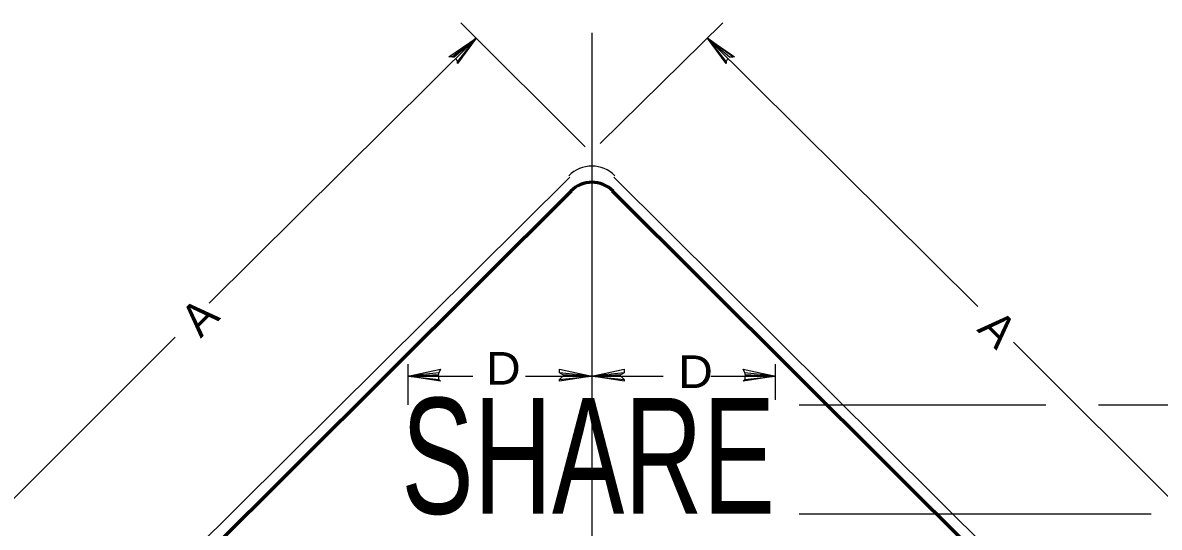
# Model space of a CAD drawing. Extents: x -0.018 to 0.195, y -0.006 to 0.263.
# Drawn here: x 0.0462 to 0.1297, y 0.1654 to 0.2025 of the extents above; entities that cross this region are included whole.
import ezdxf
from ezdxf.enums import TextEntityAlignment as Align

# ---------------------------------------------------------------- set-up
doc = ezdxf.new("R2010")
doc.units = 0
doc.header["$LTSCALE"] = 0.00096
doc.linetypes.add('DOT_DASHED', pattern=[7.7, 5, -1.2, 0.3, -1.2])
doc.layers.add('1', color=7, linetype='Continuous', lineweight=25)
doc.layers.add('12', color=7, linetype='Continuous', lineweight=13)

msp = doc.modelspace()

# ---------------------------------------------------------------- linework, layer by layer
at = {"layer": '1'}
for p, q in [((0.078375, 0.2025), (0.0875, 0.193375)), ((0.088625, 0.193625), (0.097625, 0.2025)), ((0.059875, 0.181875), (0.0795, 0.201375)), ((0.0965, 0.201375), (0.116375, 0.181625)), ((0.037, 0.159), (0.057375, 0.179375)), ((0.119, 0.179), (0.139, 0.159)), ((0.12525, 0.174375), (0.143, 0.174375)), ((0.10325, 0.166375), (0.129125, 0.166375))]:
    msp.add_line(p, q, dxfattribs=at)
at = {"layer": '1', "linetype": 'DOT_DASHED'}
msp.add_line((0.088, 0.20175), (0.088, 0.10525), dxfattribs=at)
at = {"layer": '1'}
for points in [[(0.07775, 0.2), (0.077875, 0.2), (0.0795, 0.201375), (0.07775, 0.2), (0.0775, 0.2), (0.0795, 0.201375), (0.078, 0.199875), (0.078125, 0.199625), (0.0795, 0.201375), (0.078125, 0.1995), (0.078125, 0.199625)], [(0.097875, 0.199625), (0.098, 0.199875), (0.0965, 0.201375), (0.097875, 0.199625), (0.097875, 0.1995), (0.0965, 0.201375), (0.098125, 0.2), (0.098375, 0.2), (0.0965, 0.201375), (0.0985, 0.2), (0.098375, 0.2)]]:
    msp.add_lwpolyline(points, dxfattribs=at)
at = {"layer": '12', "lineweight": 25}
for p, q in [((0.04725, 0.15225), (0.086375, 0.191125)), ((0.089625, 0.191125), (0.12875, 0.15225)), ((0.0745, 0.174375), (0.0745, 0.177375)), ((0.1015, 0.17475), (0.1015, 0.177375)), ((0.0745, 0.1765), (0.07925, 0.1765)), ((0.09675, 0.1765), (0.1015, 0.1765)), ((0.10325, 0.174375), (0.121375, 0.174375))]:
    msp.add_line(p, q, dxfattribs=at)
at = {"layer": '12', "lineweight": 60}
for p, q in [((0.048375, 0.152125), (0.0865, 0.190125)), ((0.0895, 0.190125), (0.127625, 0.152125))]:
    msp.add_line(p, q, dxfattribs=at)
at = {"layer": '12', "lineweight": 25}
for points in [[(0.07675, 0.17625), (0.07675, 0.1765), (0.0745, 0.1765), (0.07675, 0.17625), (0.076875, 0.176125), (0.0745, 0.1765), (0.07675, 0.176625), (0.07675, 0.17675), (0.0745, 0.1765), (0.076875, 0.177), (0.07675, 0.17675)], [(0.083125, 0.1765), (0.088, 0.1765), (0.09325, 0.1765)], [(0.085625, 0.17675), (0.085875, 0.176625), (0.088, 0.1765), (0.085625, 0.17675), (0.085625, 0.177), (0.088, 0.1765), (0.085875, 0.1765), (0.085625, 0.17625), (0.088, 0.1765), (0.085625, 0.176125), (0.085625, 0.17625)], [(0.090375, 0.17625), (0.090125, 0.1765), (0.088, 0.1765), (0.090375, 0.17625), (0.090375, 0.176125), (0.088, 0.1765), (0.090125, 0.176625), (0.090375, 0.17675), (0.088, 0.1765), (0.090375, 0.177), (0.090375, 0.17675)], [(0.09925, 0.17675), (0.09925, 0.176625), (0.1015, 0.1765), (0.09925, 0.17675), (0.099125, 0.177), (0.1015, 0.1765), (0.09925, 0.1765), (0.09925, 0.17625), (0.1015, 0.1765), (0.099125, 0.176125), (0.09925, 0.17625)]]:
    msp.add_lwpolyline(points, dxfattribs=at)
msp.add_arc((0.088006, 0.189548), 0.0024, 45, 135, dxfattribs=at)
at = {"layer": '12', "lineweight": 60}
msp.add_arc((0.088006, 0.188558), 0.0022, 45, 135, dxfattribs=at)

# ---------------------------------------------------------------- texts
at = {"layer": '1'}
msp.add_text('A', height=0.002399, rotation=45, dxfattribs=at).set_placement((0.060002, 0.180002), align=Align.CENTER)
at = {"layer": '12'}
msp.add_text('A', height=0.002399, rotation=315, dxfattribs=at).set_placement((0.117002, 0.179123), align=Align.CENTER)
at = {"layer": '12', "width": 1.1}
for p in [(0.0815, 0.175875), (0.095625, 0.175625)]:
    msp.add_text('D', height=0.002399, dxfattribs=at).set_placement(p, align=Align.CENTER)
at = {"layer": '12', "width": 0.7}
msp.add_text('SHARE', height=0.008517, dxfattribs=at).set_placement((0.074, 0.166375))

doc.saveas('drawing.dxf')
